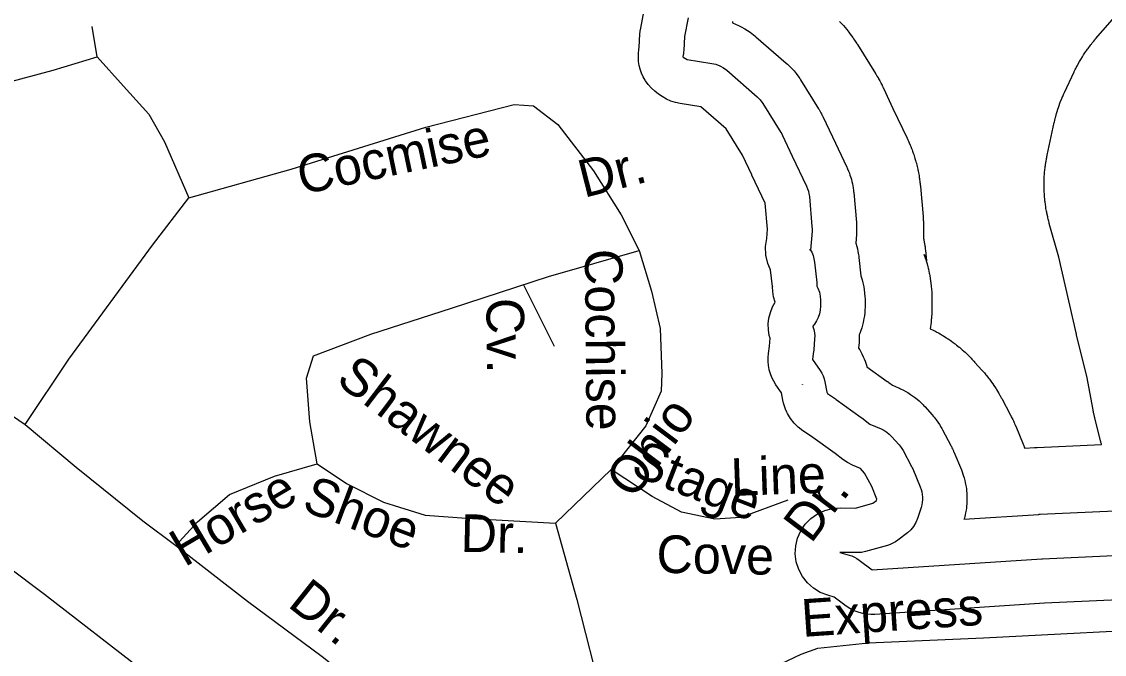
# Model space of a CAD drawing. Extents: x 2126262 to 2293712, y 749403 to 919119.
# Drawn here: x 2237261 to 2239995, y 801830 to 803427 of the extents above; entities that cross this region are included whole.
import ezdxf

# ---------------------------------------------------------------- set-up
doc = ezdxf.new("R2010")
doc.units = 0
for name, color, linetype in [('Exist Hydrographic Lake Shore', 7, 'Continuous'), ('Exist Road Non-System Type 51', 7, 'Continuous'), ('Exist Road Non-System Type 51 Label', 7, 'Continuous'), ('Exist Road Secondary Type 51 Attributed', 7, 'Continuous')]:
    doc.layers.add(name, color=color, linetype=linetype)

msp = doc.modelspace()

# ---------------------------------------------------------------- linework, layer by layer
at = {"layer": 'Exist Hydrographic Lake Shore'}
for points in [[(2240274.9, 801978.5), (2239843.6, 801958.7), (2239415.4, 801930.6), (2239405.3, 801930.4), (2239395.1, 801931.1), (2239385.1, 801932.7), (2239375.3, 801935.2), (2239365.7, 801938.6), (2239356.5, 801942.8), (2239347.7, 801947.9), (2239339.3, 801953.7), (2239312.8, 801974.2), (2239296.4, 801978.8), (2239277.4, 801986), (2239260.1, 801996.5), (2239245, 802009.9), (2239232.5, 802025.9), (2239223, 802043.8), (2239216.9, 802063.1), (2239214.4, 802083.1), (2239215.5, 802103.4), (2239220.2, 802123), (2239228.4, 802141.6), (2239239.7, 802158.3), (2239253.9, 802172.8), (2239270.4, 802184.5), (2239288.8, 802193), (2239308.3, 802198.1), (2239328.5, 802199.6), (2239366.7, 802199), (2239409.9, 802211.1), (2239419.3, 802218.4), (2239420.4, 802221.9), (2239407.5, 802253.1), (2239389.4, 802287.5), (2239379.2, 802298.9), (2239358.9, 802307.5), (2239346.4, 802313.7), (2239334.8, 802321.5), (2239314.9, 802336.6), (2239252.6, 802381.4), (2239233.1, 802394.4), (2239221.5, 802403.3), (2239211.2, 802413.6), (2239202.2, 802425.1), (2239194.9, 802437.7), (2239193, 802441.4), (2239189.7, 802448.6), (2239186.9, 802456.1), (2239184.7, 802463.8), (2239183, 802471.6), (2239179.7, 802489.7), (2239165.4, 802510.5), (2239160, 802519.3), (2239155.4, 802528.5), (2239151.6, 802538), (2239148.8, 802547.9), (2239148.6, 802548.6), (2239146.7, 802558.7), (2239145.7, 802569), (2239145.6, 802579.4), (2239146.5, 802589.7), (2239149, 802608.2), (2239150.6, 802628.1), (2239148.7, 802634.6), (2239146.5, 802649.3), (2239146.3, 802664.1), (2239148, 802678.8), (2239151.6, 802693.2), (2239157.1, 802706.9), (2239163.9, 802719.1), (2239163.8, 802719.2), (2239159.8, 802732.2), (2239157.4, 802745.5), (2239156.6, 802758), (2239156.6, 802758.1), (2239156.6, 802758.3), (2239156.6, 802757.6), (2239156.6, 802758.5), (2239152, 802800.6), (2239144.8, 802816.7), (2239139.9, 802837.8), (2239139.2, 802859.4), (2239142.4, 802879.5), (2239144.2, 802903.6), (2239138.4, 802969.2), (2239104.9, 803039.4), (2239104.7, 803039.8), (2239104.5, 803040.2), (2239081.1, 803090.1), (2239039.8, 803156.6), (2238975.7, 803212.4), (2238923.9, 803220.4), (2238912, 803222.9), (2238900.4, 803226.7), (2238889.3, 803231.7), (2238878.7, 803238), (2238869.2, 803244.3), (2238859.7, 803251.4), (2238851, 803259.4), (2238843.2, 803268.3), (2238836.4, 803278), (2238835.5, 803279.5), (2238830.5, 803288.3), (2238826.3, 803297.4), (2238823, 803306.9), (2238820.5, 803316.7), (2238818.9, 803326.6), (2238818.3, 803336.7), (2238818.5, 803346.7), (2238819.6, 803356.7), (2238820.5, 803362.7), (2238822.3, 803395.7), (2238823, 803403.2), (2238824.2, 803410.7), (2238833, 803456.6)], [(2239325.8, 803427.9), (2239328, 803425.6), (2239330.2, 803423.3), (2239335.9, 803417.1), (2239340.1, 803412.3), (2239344.1, 803407.5), (2239349.3, 803400.9), (2239351.2, 803398.4), (2239353.1, 803395.8), (2239359.7, 803386.8), (2239360.6, 803385.5), (2239361.6, 803384.2), (2239364, 803380.8), (2239365.8, 803378.2), (2239367.5, 803375.5), (2239369.8, 803372), (2239370.6, 803370.7), (2239371.5, 803369.3), (2239417, 803296.1), (2239417.3, 803295.6), (2239417.6, 803295), (2239418.5, 803293.6), (2239419.1, 803292.5), (2239419.8, 803291.5), (2239420.6, 803290), (2239420.9, 803289.5), (2239421.3, 803289), (2239423.5, 803285.1), (2239424.1, 803284.1), (2239424.7, 803283), (2239426.3, 803280.1), (2239427.6, 803277.9), (2239428.7, 803275.7), (2239430.3, 803272.7), (2239430.8, 803271.6), (2239431.4, 803270.5), (2239433.4, 803266.6), (2239433.7, 803266), (2239434, 803265.5), (2239434.7, 803264), (2239435.2, 803262.8), (2239435.8, 803261.7), (2239436.5, 803260.2), (2239436.8, 803259.7), (2239437, 803259.1), (2239460.8, 803208.3), (2239496.8, 803133.1), (2239497.2, 803132.2), (2239497.6, 803131.4), (2239498.7, 803129.1), (2239499.4, 803127.3), (2239500.2, 803125.6), (2239501.2, 803123.3), (2239501.6, 803122.4), (2239502, 803121.6), (2239504.6, 803115.4), (2239505.3, 803113.7), (2239506, 803111.9), (2239507.9, 803107.2), (2239509.3, 803103.7), (2239510.5, 803100.1), (2239512.2, 803095.4), (2239512.8, 803093.6), (2239513.4, 803091.8), (2239515.4, 803085.4), (2239516, 803083.6), (2239516.6, 803081.8), (2239518, 803077), (2239519, 803073.3), (2239520, 803069.7), (2239521.2, 803064.8), (2239521.7, 803062.9), (2239522.1, 803061.1), (2239523.6, 803054.6), (2239524, 803052.7), (2239524.4, 803050.9), (2239525.4, 803045.9), (2239526.1, 803042.2), (2239526.7, 803038.5), (2239527.5, 803033.5), (2239527.8, 803031.6), (2239528, 803029.8), (2239528.9, 803023.1), (2239529, 803022.2), (2239529.2, 803021.2), (2239529.5, 803018.7), (2239529.7, 803016.9), (2239529.9, 803015), (2239530.1, 803012.5), (2239530.2, 803011.5), (2239530.3, 803010.6), (2239537, 802935.1), (2239537, 802934.3), (2239537.1, 802933.4), (2239537.3, 802931.1), (2239537.4, 802929.4), (2239537.5, 802927.7), (2239537.6, 802925.4), (2239537.7, 802924.5), (2239537.7, 802923.6), (2239538, 802917.5), (2239538.1, 802915.8), (2239538.2, 802914.1), (2239538.3, 802909.5), (2239538.3, 802906), (2239538.3, 802902.5), (2239538.3, 802897.9), (2239538.2, 802896.2), (2239538.2, 802894.5), (2239538, 802888.4), (2239537.9, 802887.5), (2239537.9, 802886.6), (2239537.8, 802884.3), (2239537.7, 802883), (2239538.3, 802879.9), (2239538.8, 802877.5), (2239539.2, 802875.1), (2239540.7, 802866.5), (2239540.9, 802865.2), (2239541.1, 802864), (2239541.5, 802860.8), (2239541.9, 802858.4), (2239542.2, 802855.9), (2239542.6, 802852.7), (2239542.8, 802851.4), (2239542.9, 802850.2), (2239545.8, 802823.5), (2239540, 802839.6), (2239541, 802836.9), (2239541.9, 802834.1), (2239544.3, 802826.7), (2239545.9, 802821.1), (2239547.4, 802815.5), (2239549.3, 802808), (2239550, 802805.1), (2239550.6, 802802.3), (2239552.7, 802792.2), (2239553.3, 802789.3), (2239553.8, 802786.4), (2239555.1, 802778.8), (2239556, 802773), (2239556.7, 802767.3), (2239557.5, 802759.6), (2239557.8, 802756.7), (2239558, 802753.7), (2239558.8, 802743.4), (2239558.8, 802742), (2239558.9, 802740.5), (2239559.1, 802736.7), (2239559.3, 802733.7), (2239559.3, 802730.8), (2239559.4, 802727), (2239559.4, 802725.5), (2239559.4, 802724), (2239559.4, 802708.5), (2239559.4, 802707.1), (2239559.4, 802705.8), (2239559.3, 802702.2), (2239559.3, 802699.4), (2239559.2, 802696.7), (2239559, 802693.1), (2239558.9, 802691.7), (2239558.8, 802690.4), (2239558.2, 802680.8), (2239558, 802678), (2239557.8, 802675.3), (2239557.1, 802668.1), (2239556.5, 802662.7), (2239555.7, 802657.3), (2239554.8, 802651.9), (2239554.8, 802651.9), (2239562.2, 802648.3), (2239564.3, 802647.2), (2239566.4, 802646.2), (2239571.9, 802643.3), (2239575.9, 802641.1), (2239580, 802638.7), (2239585.3, 802635.6), (2239587.2, 802634.4), (2239589.2, 802633.1), (2239596.2, 802628.7), (2239598.1, 802627.4), (2239600.1, 802626.2), (2239605.2, 802622.7), (2239609, 802620.1), (2239612.7, 802617.3), (2239617.7, 802613.6), (2239619.5, 802612.2), (2239621.3, 802610.7), (2239627.7, 802605.6), (2239629.5, 802604.1), (2239631.3, 802602.6), (2239636, 802598.6), (2239639.5, 802595.5), (2239643, 802592.4), (2239647.4, 802588.1), (2239649.1, 802586.5), (2239650.8, 802584.9), (2239656.6, 802579.1), (2239657.4, 802578.3), (2239658.2, 802577.4), (2239660.4, 802575.2), (2239662, 802573.5), (2239663.6, 802571.8), (2239665.7, 802569.6), (2239666.4, 802568.7), (2239667.2, 802567.8), (2239686.1, 802546.8), (2239686.9, 802545.8), (2239687.8, 802544.8), (2239690, 802542.2), (2239691.7, 802540.3), (2239693.4, 802538.3), (2239695.5, 802535.6), (2239696.3, 802534.6), (2239697.1, 802533.6), (2239702.8, 802526.4), (2239704.4, 802524.4), (2239706, 802522.3), (2239710.1, 802516.8), (2239713.1, 802512.6), (2239715.9, 802508.3), (2239719.7, 802502.6), (2239721.1, 802500.4), (2239722.4, 802498.2), (2239727.2, 802490.4), (2239727.9, 802489.3), (2239728.5, 802488.2), (2239730.3, 802485.2), (2239731.6, 802483), (2239732.8, 802480.7), (2239734.5, 802477.7), (2239735.1, 802476.6), (2239735.7, 802475.4), (2239756.8, 802435.5), (2239757, 802435.1), (2239757.2, 802434.6), (2239757.8, 802433.5), (2239758.3, 802432.6), (2239758.7, 802431.7), (2239759.3, 802430.6), (2239759.5, 802430.1), (2239759.7, 802429.7), (2239761.3, 802426.6), (2239761.7, 802425.7), (2239762.2, 802424.8), (2239763.3, 802422.5), (2239764.1, 802420.7), (2239765, 802419), (2239766, 802416.6), (2239766.4, 802415.7), (2239766.8, 802414.8), (2239768.2, 802411.6), (2239768.4, 802411.2), (2239768.6, 802410.7), (2239769.2, 802409.5), (2239769.5, 802408.6), (2239769.9, 802407.7), (2239770.4, 802406.5), (2239770.6, 802406.1), (2239770.8, 802405.6), (2239789.7, 802360.1), (2239790, 802359.3), (2239790.4, 802358.4), (2239791.3, 802356.1), (2239792, 802354.4), (2239792.6, 802352.7), (2239793.5, 802350.4), (2239793.5, 802350.3), (2239818.1, 802351.9), (2239818.2, 802351.9), (2239818.3, 802351.9), (2239818.6, 802351.9), (2239818.8, 802351.9), (2239819, 802351.9), (2239819.3, 802351.9), (2239819.4, 802351.9), (2239819.5, 802352), (2239820.2, 802352), (2239820.5, 802352), (2239820.7, 802352), (2239821.2, 802352.1), (2239821.6, 802352.1), (2239822, 802352.1), (2239822.6, 802352.1), (2239822.8, 802352.1), (2239823, 802352.2), (2239823.7, 802352.2), (2239823.8, 802352.2), (2239823.9, 802352.2), (2239824.2, 802352.2), (2239824.4, 802352.2), (2239824.6, 802352.2), (2239824.9, 802352.2), (2239825, 802352.3), (2239825.1, 802352.3), (2239987.5, 802359.7), (2239987.1, 802361.1), (2239986.6, 802362.9), (2239986.1, 802364.7), (2239985.5, 802367.2), (2239985.2, 802368.1), (2239985, 802369), (2239970.6, 802426.7), (2239970.5, 802427.1), (2239970.4, 802427.4), (2239970.2, 802428.2), (2239970.1, 802428.8), (2239969.9, 802429.4), (2239969.7, 802430.2), (2239969.7, 802430.5), (2239969.6, 802430.8), (2239969.1, 802432.9), (2239968.9, 802433.5), (2239968.8, 802434.1), (2239968.4, 802435.8), (2239968.2, 802437), (2239967.9, 802438.2), (2239967.6, 802439.8), (2239967.4, 802440.4), (2239967.3, 802441), (2239966.9, 802443.2), (2239966.8, 802443.5), (2239966.7, 802443.8), (2239966.6, 802444.6), (2239966.5, 802445.2), (2239966.3, 802445.8), (2239966.2, 802446.7), (2239966.1, 802447), (2239966.1, 802447.3), (2239950.1, 802532.1), (2239924.7, 802635.8), (2239924.7, 802635.9), (2239924.6, 802636), (2239924.6, 802636.2), (2239924.5, 802636.4), (2239924.5, 802636.6), (2239924.4, 802636.8), (2239924.4, 802636.9), (2239924.4, 802637), (2239924.3, 802637.6), (2239924.2, 802637.7), (2239924.2, 802637.9), (2239924.1, 802638.3), (2239924, 802638.7), (2239923.9, 802639), (2239923.8, 802639.5), (2239923.8, 802639.6), (2239923.7, 802639.8), (2239923.6, 802640.4), (2239923.6, 802640.5), (2239923.5, 802640.6), (2239923.5, 802640.8), (2239923.5, 802641), (2239923.4, 802641.1), (2239923.4, 802641.4), (2239923.3, 802641.5), (2239923.3, 802641.5), (2239879.9, 802832.4), (2239855.7, 802917.9), (2239855.4, 802919.1), (2239855, 802920.4), (2239854.1, 802923.7), (2239853.5, 802926.2), (2239852.9, 802928.7), (2239852.1, 802932), (2239851.8, 802933.3), (2239851.6, 802934.5), (2239849.6, 802943.5), (2239849.1, 802946), (2239848.6, 802948.5), (2239847.3, 802955.3), (2239846.5, 802960.4), (2239845.8, 802965.5), (2239844.9, 802972.3), (2239844.6, 802974.8), (2239844.4, 802977.4), (2239843.5, 802986.5), (2239843.3, 802989.1), (2239843.1, 802991.7), (2239842.7, 802998.5), (2239842.5, 803003.7), (2239842.4, 803008.8), (2239842.4, 803015.7), (2239842.4, 803018.3), (2239842.5, 803020.8), (2239842.7, 803030), (2239842.8, 803032.6), (2239843, 803035.1), (2239843.4, 803042), (2239843.8, 803047.1), (2239844.3, 803052.2), (2239845.1, 803059.1), (2239845.5, 803061.6), (2239845.9, 803064.2), (2239847.2, 803073.2), (2239847.4, 803074.5), (2239847.6, 803075.8), (2239848.2, 803079.1), (2239848.7, 803081.7), (2239849.2, 803084.2), (2239849.8, 803087.6), (2239850.1, 803088.8), (2239850.4, 803090.1), (2239868.1, 803172.2), (2239868.4, 803173.4), (2239868.6, 803174.5), (2239869.3, 803177.6), (2239869.9, 803179.9), (2239870.5, 803182.2), (2239871.3, 803185.3), (2239871.6, 803186.4), (2239871.9, 803187.6), (2239874.1, 803195.7), (2239874.8, 803198), (2239875.4, 803200.3), (2239877.3, 803206.3), (2239878.8, 803210.8), (2239880.3, 803215.3), (2239882.5, 803221.2), (2239883.4, 803223.5), (2239884.2, 803225.7), (2239887.4, 803233.5), (2239887.8, 803234.6), (2239888.3, 803235.7), (2239889.5, 803238.6), (2239890.4, 803240.8), (2239891.4, 803243), (2239892.7, 803245.8), (2239893.2, 803246.9), (2239893.7, 803248), (2239918.1, 803300.2), (2239918.7, 803301.5), (2239919.4, 803302.8), (2239921.1, 803306.4), (2239922.4, 803309), (2239923.8, 803311.6), (2239925.6, 803315.1), (2239926.3, 803316.4), (2239927.1, 803317.7), (2239932.2, 803326.9), (2239933.6, 803329.4), (2239935.1, 803332), (2239939.2, 803338.7), (2239942.3, 803343.7), (2239945.6, 803348.6), (2239950.2, 803355.1), (2239951.9, 803357.5), (2239953.7, 803359.8), (2239960, 803368.2), (2239960.9, 803369.4), (2239961.8, 803370.5), (2239964.2, 803373.6), (2239966.1, 803375.9), (2239967.9, 803378.2), (2239970.5, 803381.2), (2239971.4, 803382.4), (2239972.4, 803383.5), (2240033.4, 803453.4)], [(2238943.7, 803436.7), (2238934.7, 803389.5), (2238932.7, 803354.6), (2238932.4, 803350.9), (2238931.9, 803347.2), (2238930.7, 803339.4), (2238931.7, 803337.9), (2238941.1, 803331.6), (2239003.6, 803321.9), (2239013.8, 803319.6), (2239023.7, 803315.8), (2239032.9, 803310.7), (2239041.3, 803304.4), (2239117.9, 803237.8), (2239125.8, 803229.8), (2239132.4, 803220.8), (2239177.9, 803147.5), (2239180.1, 803143.7), (2239182.1, 803139.8), (2239206.4, 803087.9), (2239242.8, 803011.6), (2239245.5, 803005.4), (2239247.5, 802999), (2239249, 802992.5), (2239249.9, 802985.8), (2239256.5, 802910.4), (2239256.8, 802904.3), (2239256.6, 802898.1), (2239253, 802850.1), (2239251.5, 802852.4), (2239255.8, 802844.8), (2239259.2, 802836.8), (2239261.6, 802828.4), (2239263.1, 802819.8), (2239268.6, 802768.8), (2239268.9, 802764.7), (2239269, 802760.7), (2239269, 802759.1), (2239271.6, 802754.2), (2239275.1, 802744.5), (2239277.2, 802734.3), (2239277.9, 802724), (2239277.9, 802708.5), (2239277.3, 802698.9), (2239275.4, 802689.4), (2239272.4, 802680.2), (2239268.2, 802671.6), (2239262.9, 802663.5), (2239258.6, 802658.5), (2239259.1, 802657.3), (2239261.4, 802649.7), (2239262.8, 802641.9), (2239263.5, 802633.9), (2239263.3, 802626), (2239261, 802598.2), (2239260.9, 802596.3), (2239260.6, 802594.3), (2239258, 802574.8), (2239258.2, 802574.2), (2239277, 802546.8), (2239281.1, 802540), (2239284.5, 802532.9), (2239287.1, 802525.4), (2239288.9, 802517.8), (2239293.7, 802491.7), (2239295.5, 802488), (2239315.5, 802474.6), (2239316.6, 802473.9), (2239317.7, 802473.1), (2239381, 802427.6), (2239381.8, 802427), (2239382.6, 802426.5), (2239402.8, 802411), (2239430.8, 802399.2), (2239438.2, 802395.5), (2239445.2, 802391.1), (2239451.6, 802386), (2239457.4, 802380.1), (2239476.3, 802359.1), (2239482, 802351.9), (2239486.7, 802344.1), (2239507.8, 802304.1), (2239509.4, 802301), (2239510.8, 802297.8), (2239529.6, 802252.3), (2239531.9, 802246.1), (2239533.6, 802239.8), (2239534.7, 802233.3), (2239535.3, 802226.7), (2239535.3, 802220.1), (2239534.7, 802213.6), (2239533.5, 802207.1), (2239531.8, 802200.7), (2239522.9, 802173), (2239518.7, 802162.5), (2239512.9, 802152.8), (2239505.7, 802144.1), (2239497.3, 802136.5), (2239472.9, 802117.7), (2239467, 802113.5), (2239460.7, 802110), (2239454.1, 802107.1), (2239447.3, 802104.8), (2239391.8, 802089.2), (2239381.2, 802087.1), (2239370.4, 802086.5), (2239326.8, 802087.1), (2239350.3, 802080.5), (2239357.1, 802078.3), (2239363.6, 802075.4), (2239369.9, 802071.8), (2239375.8, 802067.7), (2239408.1, 802042.8), (2239836.6, 802071), (2239837.3, 802071), (2239838.1, 802071.1), (2240271.9, 802091)], [(2239056.1, 803427.9), (2239056, 803426.9), (2239055.6, 803424.2), (2239055.6, 803424), (2239063.8, 803420.9), (2239071.1, 803417.8), (2239078.1, 803414.3), (2239087.3, 803409.2), (2239094.1, 803405.1), (2239100.6, 803400.6), (2239109, 803394.2), (2239112.1, 803391.8), (2239115.1, 803389.3), (2239191.7, 803322.7), (2239194.8, 803319.9), (2239197.8, 803316.9), (2239205.7, 803309), (2239211.4, 803302.8), (2239216.6, 803296.2), (2239223.2, 803287.1), (2239225.6, 803283.7), (2239227.9, 803280.1), (2239273.4, 803206.9), (2239274.3, 803205.5), (2239275.1, 803204.1), (2239277.4, 803200.2), (2239279, 803197.3), (2239280.5, 803194.4), (2239282.5, 803190.4), (2239283.3, 803189), (2239284, 803187.5), (2239308.1, 803136), (2239344.3, 803060.1), (2239345.4, 803057.9), (2239346.4, 803055.6), (2239349, 803049.4), (2239350.9, 803044.7), (2239352.5, 803039.9), (2239354.6, 803033.6), (2239356, 803028.7), (2239357.3, 803023.8), (2239358.7, 803017.3), (2239359.7, 803012.4), (2239360.5, 803007.4), (2239361.4, 803000.7), (2239361.7, 802998.2), (2239362, 802995.7), (2239368.6, 802920.3), (2239368.8, 802918), (2239368.9, 802915.7), (2239369.2, 802909.6), (2239369.3, 802905), (2239369.3, 802900.4), (2239369.1, 802894.2), (2239369, 802891.9), (2239368.8, 802889.6), (2239367.2, 802868.3), (2239367.2, 802868.2), (2239369.6, 802859.8), (2239371.3, 802853.5), (2239372.6, 802847.1), (2239374, 802838.5), (2239374.5, 802835.2), (2239374.9, 802832), (2239380, 802785.2), (2239381, 802782.5), (2239383.3, 802775.1), (2239385.2, 802767.6), (2239387.3, 802757.5), (2239388.6, 802749.8), (2239389.4, 802742.1), (2239390.2, 802731.8), (2239390.4, 802727.9), (2239390.4, 802724), (2239390.4, 802708.5), (2239390.4, 802704.9), (2239390.2, 802701.3), (2239389.6, 802691.6), (2239388.9, 802684.4), (2239387.7, 802677.3), (2239385.9, 802667.8), (2239384.2, 802660.7), (2239382.2, 802653.8), (2239379.1, 802644.6), (2239376.6, 802637.8), (2239375.9, 802636.3), (2239375.9, 802630.9), (2239375.7, 802623), (2239375.6, 802620), (2239375.4, 802617), (2239374.3, 802603.2), (2239377.1, 802598.7), (2239380.1, 802593.5), (2239382.7, 802588.2), (2239386.1, 802581.1), (2239388.5, 802575.7), (2239390.6, 802570.2), (2239393.2, 802562.7), (2239395.1, 802557.1), (2239395.4, 802555.8), (2239446.7, 802519), (2239447, 802518.7), (2239447.3, 802518.5), (2239448.1, 802517.9), (2239448.7, 802517.5), (2239449.3, 802517.1), (2239450, 802516.5), (2239450.3, 802516.2), (2239450.6, 802516), (2239459.7, 802509.1), (2239474.8, 802502.7), (2239477.6, 802501.5), (2239480.4, 802500.2), (2239487.8, 802496.5), (2239493.3, 802493.7), (2239498.6, 802490.5), (2239505.5, 802486.1), (2239510.6, 802482.6), (2239515.6, 802478.9), (2239522, 802473.7), (2239526.7, 802469.7), (2239531.2, 802465.5), (2239537, 802459.6), (2239539.2, 802457.4), (2239541.3, 802455.2), (2239560.1, 802434.1), (2239562.4, 802431.5), (2239564.6, 802428.8), (2239570.2, 802421.6), (2239574.3, 802416.1), (2239578.1, 802410.4), (2239582.8, 802402.5), (2239584.6, 802399.6), (2239586.2, 802396.6), (2239607.3, 802356.6), (2239607.9, 802355.5), (2239608.5, 802354.3), (2239610, 802351.2), (2239611.2, 802348.8), (2239612.3, 802346.5), (2239613.7, 802343.3), (2239614.2, 802342.1), (2239614.7, 802340.9), (2239633.6, 802295.4), (2239634.5, 802293.1), (2239635.3, 802290.8), (2239637.6, 802284.6), (2239639.2, 802279.9), (2239640.6, 802275.2), (2239642.3, 802268.8), (2239643.4, 802264), (2239644.4, 802259.2), (2239645.5, 802252.7), (2239646.3, 802247.8), (2239646.8, 802242.9), (2239647.4, 802236.3), (2239647.7, 802231.4), (2239647.8, 802226.5), (2239647.8, 802219.9), (2239647.7, 802215), (2239647.3, 802210), (2239646.7, 802203.5), (2239646.2, 802198.6), (2239645.4, 802193.7), (2239644.2, 802187.2), (2239643.3, 802182.3), (2239642.1, 802177.6), (2239640.3, 802171.2), (2239640.2, 802170.8), (2239829.2, 802183.2), (2239829.5, 802183.2), (2239829.8, 802183.3), (2239830.5, 802183.3), (2239831, 802183.3), (2239831.6, 802183.4), (2239832.3, 802183.4), (2239832.6, 802183.4), (2239832.9, 802183.4), (2240266.7, 802203.4)]]:
    msp.add_lwpolyline(points, dxfattribs=at)
msp.add_lwpolyline([(2239232.7, 802510.5), (2239232.6, 802510.7), (2239232.7, 802510.5)], close=True, dxfattribs=at)
at = {"layer": 'Exist Road Non-System Type 51'}
msp.add_line((2237451.6, 803338.6), (2237439.7, 803414.7), dxfattribs=at)
for points in [[(2237062.9, 803291.8), (2237150.9, 803270.9), (2237224.8, 803273.7), (2237340.6, 803304.4), (2237451.6, 803338.6)], [(2237451.6, 803338.6), (2237518.6, 803264.6), (2237582.8, 803193.4), (2237621.8, 803123.5), (2237683.2, 802982.5), (2237942.1, 803054.4), (2238281.9, 803161.2), (2238504.5, 803217.8), (2238553.3, 803215), (2238614.7, 803167.5), (2238705.4, 803050.2), (2238774.5, 802939.2), (2238820.6, 802849.8)], [(2236480.3, 803239.5), (2236505.4, 803112.4), (2236557.1, 802986.7), (2236589.2, 802939.2), (2236706.4, 802842.8), (2237085.3, 802536.2), (2237270.2, 802409.8)], [(2237270.2, 802409.8), (2237380.4, 802574.6), (2237591.8, 802863.1), (2237683.2, 802982.5)], [(2238007, 802310.7), (2237988.9, 802416.8), (2237980.5, 802527.2), (2237997.9, 802583.7), (2238143.1, 802638.2), (2238346.8, 802703.8), (2238591.7, 802784.1), (2238820.6, 802849.8)], [(2238820.6, 802849.8), (2238851.3, 802746.4), (2238872.9, 802652.2), (2238877.1, 802539), (2238875.7, 802494.3), (2238837.3, 802407), (2238749.4, 802296.7), (2238609.1, 802160.5)], [(2238606.4, 802606.7), (2238528.1, 802763.3)], [(2237270.2, 802409.8), (2237398.6, 802302.3), (2237567.4, 802166.8), (2237650.4, 802104.7)], [(2237650.4, 802104.7), (2237704.9, 802164.7), (2237785.8, 802233.1), (2237899.5, 802279.9), (2238007, 802310.7)], [(2238007, 802310.7), (2238081.7, 802261.1), (2238175.1, 802213.6), (2238279.8, 802181.5), (2238384.8, 802173.4), (2238609.1, 802160.5)], [(2239195.8, 802219.4), (2239077, 802175.4), (2239011, 802171), (2238927.5, 802188.6), (2238852.7, 802228.2), (2238749.4, 802296.7)], [(2238609.1, 802160.5), (2238662.9, 801967.8), (2238727.8, 801714.3)], [(2237650.4, 802104.7), (2237831.9, 801964.3), (2238020.2, 801824.6), (2238128.4, 801738.7), (2238210.7, 801620)], [(2239005.3, 801719.9), (2239062.5, 801750.7), (2239146.1, 801790.3), (2239229.6, 801829.9), (2239271.4, 801845.3), (2239399, 801858.5), (2239689.3, 801871.7), (2240210.5, 801898.1)]]:
    msp.add_lwpolyline(points, dxfattribs=at)
at = {"layer": 'Exist Road Secondary Type 51 Attributed'}
msp.add_lwpolyline([(2237710.7, 800619.2), (2237931.6, 801030), (2237953.9, 801146), (2237953.2, 801277.9), (2237937.9, 801379.9), (2237896, 801493), (2237819.3, 801593.6), (2237319, 801981.2), (2237039.9, 802190.7)], dxfattribs=at)

# ---------------------------------------------------------------- texts
at = {"layer": 'Exist Road Non-System Type 51 Label'}
for s, rotation, p in [('Cocmise', 11.8421, (2237968.3, 802990.2)), ('Dr.', 14.2324, (2238681, 802982)), ('Cochise', 270.5215, (2238683.1, 802853)), ('Cv.', 270.5215, (2238434.5, 802729.2)), ('Shawnee', 322.9166, (2238051.6, 802516.3)), ('Ohio', 53.0328, (2238805.2, 802218)), ('Stage', 338.7369, (2238795.6, 802284.2)), ('Line', 2.0256, (2239052.9, 802229.5)), ('Horse', 30.5375, (2237672.7, 802048.8)), ('Shoe', 339.4151, (2237965.5, 802194.6)), ('Dr.', 53.0328, (2239254.1, 802107)), ('Dr.', 358.7071, (2238368.8, 802088.8)), ('Cove', 359.0062, (2238863.4, 802035.7)), ('Dr.', 321.5409, (2237930.2, 801952.4)), ('Express', 3.8854, (2239232.7, 801873.6))]:
    msp.add_text(s, height=95, rotation=rotation, dxfattribs=at).set_placement(p)

doc.saveas('drawing.dxf')
